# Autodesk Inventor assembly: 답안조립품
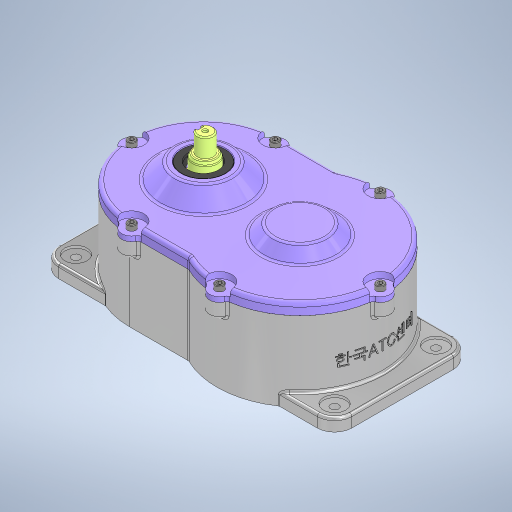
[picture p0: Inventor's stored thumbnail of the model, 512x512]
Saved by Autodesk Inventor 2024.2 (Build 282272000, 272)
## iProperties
Created: 2025-09
Part Number: 답안조립품
Document SubType Name: Assembly
Designer: home
Author: home
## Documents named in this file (19)
- C:\Users\home\Desktop\750903V1008\답안조립품.iam
- C:\Users\home\Desktop\750903V1008\본체.ipt
- C:\Users\home\Desktop\750903V1008\슬롯 축\슬롯 축.ipt
- C:\Users\home\Desktop\750903V1008\깊은 홈 볼 베어링 6904\깊은 홈 볼 베어링 6904.ipt
- C:\Users\home\Desktop\750903V1008\6각 구멍붙이 볼트 M6x12\6각 구멍붙이 볼트 M6x12.ipt
- C:\Users\home\Desktop\750903V1008\어댑터\어댑터.ipt
- C:\Users\home\Desktop\750903V1008\평행 키 6x6x14\평행 키 6x6x14.ipt
- C:\Users\home\Desktop\750903V1008\슬롯\슬롯.ipt
- C:\Users\home\Desktop\750903V1008\칼라\칼라.ipt
- C:\Users\home\Desktop\750903V1008\커버\커버.ipt
- C:\Users\home\Desktop\750903V1008\오일 실 20 35 8\오일 실 20 35 8.ipt
- C:\Users\home\Desktop\750903V1008\스러스트 볼 베어링 51102\스러스트 볼 베어링 51102.ipt
- C:\Users\home\Desktop\750903V1008\구동 축\구동 축.ipt
- C:\Users\home\Desktop\750903V1008\구동 휠\구동 휠.ipt
- C:\Users\home\Desktop\750903V1008\캠 플로워\캠 플로워.ipt
- C:\Users\home\Desktop\750903V1008\평 와셔 M3\평 와셔 M3.ipt
- C:\Users\home\Desktop\750903V1008\스프링 와셔 M3\스프링 와셔 M3.ipt
- C:\Users\home\Desktop\750903V1008\육각 너트 M3\육각 너트 M3.ipt
- C:\Users\home\Desktop\750903V1008\6각 구멍붙이 볼트 M4x10\6각 구멍붙이 볼트 M4x10.ipt
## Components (9 placed, 4 different names)
1. 6각 구멍붙이 볼트 M6x12:1
2. 구동 축:1 — 각도:2
3. 구동 휠:1
4. 6각 구멍붙이 볼트 M4x10:1
5. 6각 구멍붙이 볼트 M4x10:2
6. 6각 구멍붙이 볼트 M4x10:3
7. 6각 구멍붙이 볼트 M4x10:4
8. 6각 구멍붙이 볼트 M4x10:5
9. 6각 구멍붙이 볼트 M4x10:6
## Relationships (1: Angle 1)
- 각도:2 [Angle]: 구동 축:1
